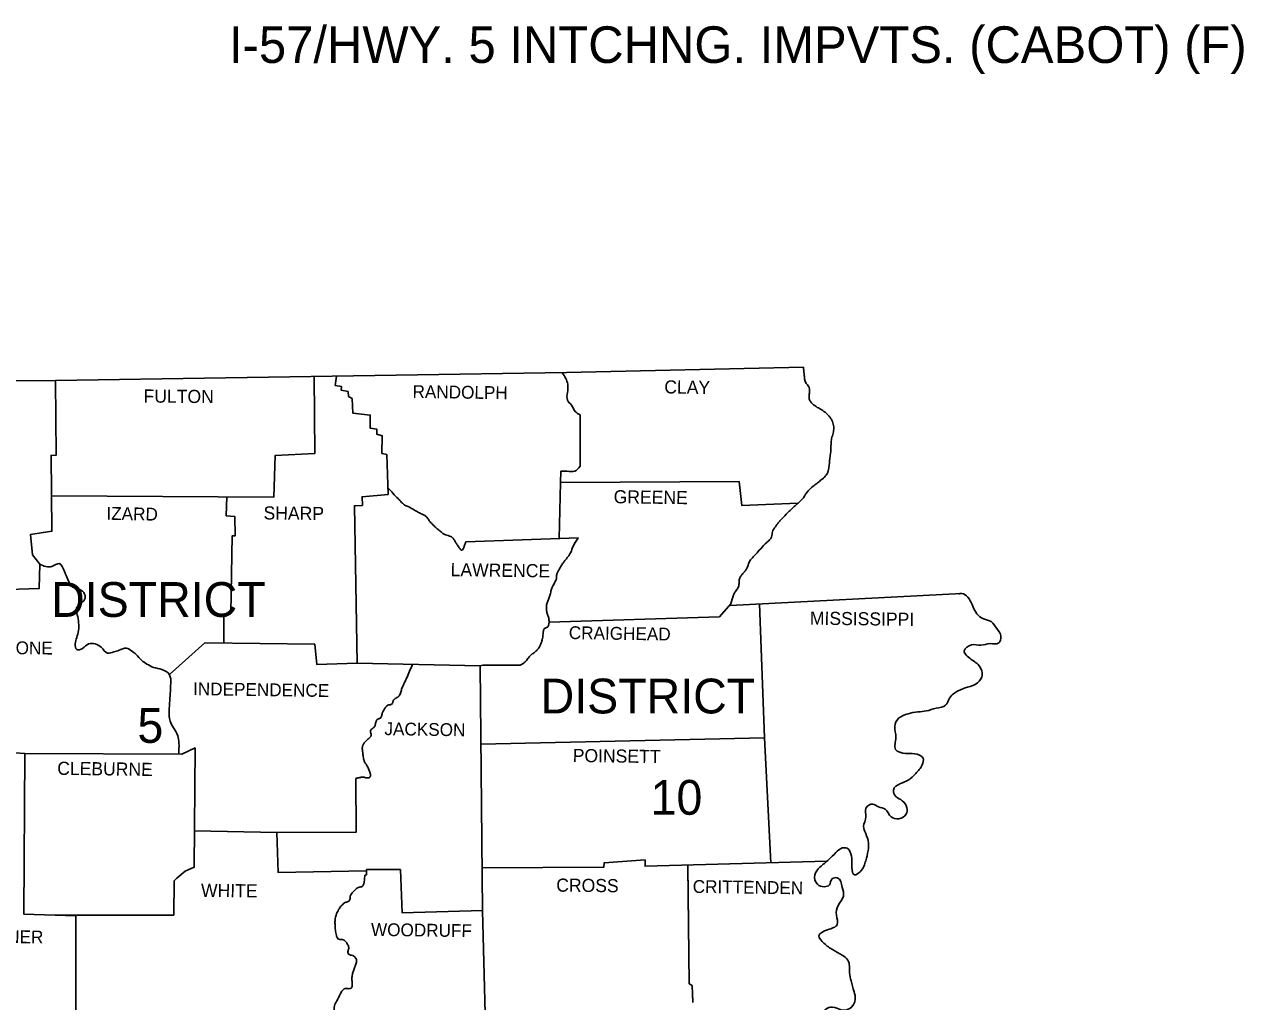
# Model space of a CAD drawing. Extents: x 1373878 to 1386598, y 1168333 to 1170533.
# Drawn here: x 1376588.9 to 1376988.4, y 1170078.1 to 1170398.3 of the extents above; entities that cross this region are included whole.
import ezdxf

# ---------------------------------------------------------------- set-up
doc = ezdxf.new("R2010")
doc.units = 0
for name, color, linetype in [('1', 7, 'Continuous'), ('Default', 7, 'Continuous'), ('G-ANNO-TEXT', 7, 'Continuous')]:
    doc.layers.add(name, color=color, linetype=linetype)

msp = doc.modelspace()

# ---------------------------------------------------------------- linework, layer by layer
at = {"layer": '1'}
for p, q in [((1376820.19, 1170207.9), (1376821.27, 1170211.22)), ((1376700.99, 1170121.31), (1376712.17, 1170121.31))]:
    msp.add_line(p, q, dxfattribs=at)
for points in [[(1376295.59, 1170281.4), (1376457.29, 1170281.3), (1376599.19, 1170281.6), (1376766.59, 1170284.2), (1376844.19, 1170286)], [(1376599.19, 1170281.6), (1376599.39, 1170257.2), (1376597.69, 1170257.1), (1376597.99, 1170232.2), (1376590.99, 1170231.2), (1376591.59, 1170224.5), (1376593.99, 1170221.4), (1376593.79, 1170213.5), (1376580.19, 1170213), (1376579.69, 1170200.8), (1376567.29, 1170200.4), (1376566.69, 1170185.61), (1376567.39, 1170184.41), (1376567.69, 1170160.81), (1376589.09, 1170159.41), (1376588.79, 1170106.71), (1376605.79, 1170106.21), (1376605.79, 1170052.61), (1376592.39, 1170051.61), (1376591.39, 1170039.81), (1376568.89, 1170039.71)], [(1376691.17, 1170283.03), (1376690.79, 1170280), (1376692.79, 1170279.7), (1376692.69, 1170278.5), (1376694.99, 1170278), (1376695.19, 1170276.4), (1376696.29, 1170275.7), (1376696.59, 1170270.9), (1376702.29, 1170270.3), (1376702.29, 1170266), (1376704.39, 1170265.7), (1376704.39, 1170264), (1376706.19, 1170263.5), (1376706.09, 1170257.7), (1376707.69, 1170257.4), (1376708.09, 1170244.3), (1376699.59, 1170243.5), (1376699.69, 1170240.7), (1376697.09, 1170240.6), (1376697.99, 1170189.01), (1376738.29, 1170188.11), (1376738.99, 1170107.91), (1376712.69, 1170107.21), (1376712.17, 1170121.31)], [(1376820.19, 1170207.9), (1376896.09, 1170211.8)], [(1376700.99, 1170121.31), (1376700.99, 1170119.61), (1376700.49, 1170119.51)], [(1376738.87, 1170121.9), (1376778.79, 1170122.11), (1376778.89, 1170123.51), (1376792.29, 1170124.51), (1376792.29, 1170122.41), (1376851.86, 1170124.04)]]:
    msp.add_lwpolyline(points, dxfattribs=at)
for points in [[(1376844.19, 1170286), (1376844.28, 1170284.9), (1376844.39, 1170283.8), (1376844.53, 1170282.7), (1376844.69, 1170281.6), (1376844.93, 1170280.98), (1376845.33, 1170280.42), (1376845.77, 1170279.88), (1376846.09, 1170279.3), (1376846.22, 1170278.29), (1376846.1, 1170277.19), (1376846.02, 1170276.1), (1376846.09, 1170275.59), (1376846.29, 1170275.1), (1376847.05, 1170274.12), (1376847.99, 1170273.3), (1376848.71, 1170272.83), (1376849.45, 1170272.41), (1376850.18, 1170271.99), (1376850.89, 1170271.5), (1376852.34, 1170270.22), (1376852.95, 1170269.48), (1376853.23, 1170269.06), (1376853.49, 1170268.6), (1376853.86, 1170267.76), (1376854.07, 1170266.9), (1376854.14, 1170266.05), (1376854.09, 1170265.2), (1376853.92, 1170264.33), (1376853.67, 1170263.46), (1376853.44, 1170262.59), (1376853.29, 1170261.7), (1376853.24, 1170260.73), (1376853.2, 1170259.76), (1376853.16, 1170258.78), (1376853.09, 1170257.8), (1376852.69, 1170254.4), (1376852.51, 1170252.84), (1376852.35, 1170252.07), (1376852.24, 1170251.68), (1376852.09, 1170251.3), (1376851.05, 1170249.92), (1376849.69, 1170248.8), (1376849.12, 1170248.35), (1376848.54, 1170247.91), (1376847.96, 1170247.47), (1376847.39, 1170247), (1376845.29, 1170244.9), (1376844.9, 1170244.36), (1376844.56, 1170243.78), (1376844.21, 1170243.21), (1376843.79, 1170242.7), (1376841.19, 1170240.3), (1376838.59, 1170237.8), (1376836.49, 1170235.6), (1376835.92, 1170234.94), (1376835.38, 1170234.25), (1376834.88, 1170233.53), (1376834.39, 1170232.8), (1376834.09, 1170232.05), (1376833.94, 1170231.22), (1376833.77, 1170230.41), (1376833.62, 1170230.04), (1376833.39, 1170229.7), (1376832.84, 1170229.13), (1376832.25, 1170228.6), (1376831.65, 1170228.07), (1376831.09, 1170227.5), (1376829.29, 1170225.5), (1376826.89, 1170222.8), (1376826.5, 1170222.19), (1376826.23, 1170221.49), (1376825.99, 1170220.78), (1376825.69, 1170220.1), (1376825.16, 1170219.31), (1376824.53, 1170218.57), (1376823.91, 1170217.81), (1376823.39, 1170217), (1376823.18, 1170216.29), (1376823.12, 1170215.51), (1376823.07, 1170214.73), (1376822.89, 1170214), (1376822.57, 1170213.38), (1376822.17, 1170212.79), (1376821.76, 1170212.2), (1376821.39, 1170211.6), (1376821.27, 1170211.22)], [(1376894.99, 1170211.7), (1376896.09, 1170211.8), (1376899.49, 1170208.2), (1376900.99, 1170205.2), (1376903.19, 1170203.5), (1376905.69, 1170202.6), (1376907.59, 1170200.3), (1376908.89, 1170197.8), (1376908.19, 1170195.6), (1376905.39, 1170195.4), (1376902.29, 1170194.9), (1376899.29, 1170195), (1376896.89, 1170193), (1376899.09, 1170190.31), (1376901.99, 1170187.81), (1376902.79, 1170185.11), (1376901.19, 1170182.51), (1376897.99, 1170181.11), (1376894.89, 1170179.91), (1376892.09, 1170177.51), (1376890.79, 1170175.21), (1376887.69, 1170174.21), (1376884.49, 1170173.31), (1376881.69, 1170173.01), (1376878.49, 1170172.41), (1376875.39, 1170170.91), (1376874.09, 1170168.31), (1376874.49, 1170164.61), (1376874.39, 1170160.71), (1376877.69, 1170159.41), (1376880.59, 1170159.31), (1376883.39, 1170157.81), (1376883.09, 1170155.61), (1376880.99, 1170152.81), (1376878.49, 1170150.61), (1376875.99, 1170149.51), (1376873.69, 1170147.41), (1376874.49, 1170145.31), (1376876.59, 1170143.91), (1376878.09, 1170141.61), (1376877.89, 1170139.51), (1376875.49, 1170138.01), (1376872.89, 1170138.61), (1376870.99, 1170141.11), (1376868.79, 1170141.91), (1376866.89, 1170142.81), (1376864.69, 1170141.51), (1376864.69, 1170138.61), (1376863.89, 1170135.51), (1376864.59, 1170133.21), (1376865.49, 1170130.01), (1376865.39, 1170127.61), (1376864.59, 1170124.21), (1376862.89, 1170120.71), (1376860.89, 1170119.61), (1376860.09, 1170123.41), (1376859.69, 1170126.51), (1376858.49, 1170128.31), (1376856.89, 1170128.41), (1376854.79, 1170126.91), (1376852.49, 1170124.61), (1376849.59, 1170122.11), (1376847.89, 1170119.61), (1376848.79, 1170116.51), (1376850.99, 1170115.71), (1376852.69, 1170116.31), (1376853.59, 1170118.31), (1376855.29, 1170118.61), (1376856.89, 1170115.51)], [(1376700.49, 1170119.51), (1376700.43, 1170118.68), (1376700.36, 1170117.85), (1376700.22, 1170117.02), (1376700.12, 1170116.61), (1376700.06, 1170116.41), (1376699.99, 1170116.21), (1376699.67, 1170115.84), (1376699.16, 1170115.66), (1376698.59, 1170115.53), (1376698.32, 1170115.44), (1376698.09, 1170115.31), (1376696.92, 1170114.28), (1376695.89, 1170113.11), (1376695.7, 1170112.64), (1376695.66, 1170112.09), (1376695.6, 1170111.56), (1376695.39, 1170111.11), (1376695.21, 1170110.95), (1376695, 1170110.84), (1376694.51, 1170110.7), (1376694.01, 1170110.56), (1376693.59, 1170110.31), (1376693.12, 1170109.83), (1376692.67, 1170109.33), (1376692.26, 1170108.79), (1376691.89, 1170108.21), (1376691.21, 1170106.79), (1376690.79, 1170105.31), (1376690.71, 1170103.81), (1376690.79, 1170102.31), (1376690.86, 1170101.44), (1376690.98, 1170100.59), (1376691.18, 1170099.74), (1376691.32, 1170099.32), (1376691.49, 1170098.91), (1376691.96, 1170098.51), (1376692.65, 1170098.39), (1376693.39, 1170098.31), (1376693.99, 1170098.01), (1376694.19, 1170097.78), (1376694.38, 1170097.55), (1376694.7, 1170097.05), (1376695.19, 1170096.01), (1376695.22, 1170095.49), (1376695.07, 1170094.94), (1376694.94, 1170094.4), (1376694.99, 1170093.91), (1376695.46, 1170093.47), (1376696.15, 1170093.23), (1376696.86, 1170092.98), (1376697.39, 1170092.51), (1376697.57, 1170092.21), (1376697.72, 1170091.91), (1376697.81, 1170091.61), (1376697.79, 1170091.31), (1376697.39, 1170090.01), (1376696.29, 1170086.31), (1376696.22, 1170085.69), (1376696.27, 1170085.07), (1376696.35, 1170084.44), (1376696.39, 1170083.81), (1376696.35, 1170083.25), (1376696.29, 1170082.98), (1376696.19, 1170082.71), (1376695.67, 1170082.33), (1376694.87, 1170082.32), (1376694.06, 1170082.33), (1376693.49, 1170082.01), (1376691.89, 1170079.31), (1376690.79, 1170077.41), (1376690.66, 1170077.1), (1376690.45, 1170076.16), (1376690.41, 1170075.54), (1376690.39, 1170074.91), (1376690.44, 1170074.46), (1376690.57, 1170074.01), (1376690.68, 1170073.56), (1376690.69, 1170073.11), (1376690.55, 1170072.74), (1376690.32, 1170072.4), (1376690.07, 1170072.06), (1376689.89, 1170071.71), (1376689.81, 1170071.19), (1376689.8, 1170070.65), (1376689.75, 1170070.11), (1376689.59, 1170069.61), (1376688.59, 1170067.81), (1376687.69, 1170066.11), (1376687.73, 1170065.62), (1376688.12, 1170065.12), (1376688.55, 1170064.62), (1376688.69, 1170064.11), (1376688.55, 1170063.42), (1376688.39, 1170062.71), (1376688.24, 1170062.15), (1376688.06, 1170061.6), (1376687.79, 1170060.51)], [(1376856.89, 1170115.51), (1376857.29, 1170112.61), (1376855.59, 1170109.51), (1376854.99, 1170106.41), (1376855.29, 1170103.31), (1376852.09, 1170101.61), (1376849.29, 1170099.61), (1376850.89, 1170097.21), (1376853.89, 1170095.01), (1376856.89, 1170093.31), (1376858.79, 1170091.61), (1376859.29, 1170087.51), (1376859.79, 1170084.91), (1376860.79, 1170081.31), (1376861.19, 1170078.81), (1376859.39, 1170075.81), (1376857.29, 1170075.21), (1376855.09, 1170075.91), (1376852.49, 1170076.11), (1376850.39, 1170074.11), (1376848.89, 1170071.31), (1376847.39, 1170068.51), (1376846.29, 1170066.11), (1376845.19, 1170063.51), (1376842.99, 1170060.51), (1376840.29, 1170060.01), (1376837.09, 1170059.21), (1376835.19, 1170057.01), (1376835.49, 1170053.31), (1376837.29, 1170050.81), (1376838.69, 1170047.71), (1376839.69, 1170045.01), (1376839.19, 1170041.61), (1376837.79, 1170039.11), (1376835.99, 1170037.61), (1376835.19, 1170034.41), (1376833.89, 1170032.01), (1376832.69, 1170031.21), (1376830.29, 1170031.41), (1376827.69, 1170031.91), (1376825.49, 1170031.71), (1376823.39, 1170030.61), (1376821.29, 1170031.31), (1376819.09, 1170033.71), (1376817.29, 1170035.51), (1376815.29, 1170036.21), (1376813.19, 1170035.11), (1376812.79, 1170031.81), (1376813.79, 1170028.41), (1376814.69, 1170023.81), (1376813.79, 1170021.01), (1376813.49, 1170016.41)]]:
    msp.add_spline(points, degree=3, dxfattribs=at)
at = {"layer": 'Default'}
msp.add_line((1376764.6, 1170248.2), (1376764.69, 1170251.9), dxfattribs=at)
for points in [[(1376683.89, 1170282.92), (1376684.09, 1170257.7), (1376671.09, 1170257), (1376670.69, 1170243.4), (1376597.85, 1170243.81)], [(1376770.99, 1170270.4), (1376770.99, 1170253.5)], [(1376764.17, 1170229.88), (1376764.6, 1170248.2), (1376764.69, 1170248.2), (1376823.19, 1170248.5), (1376823.99, 1170240.7), (1376842.34, 1170241.37)], [(1376655.31, 1170243.49), (1376655.09, 1170237.3), (1376657.89, 1170237.1), (1376657.99, 1170230.7), (1376656.99, 1170230.7), (1376656.59, 1170205.5), (1376654.29, 1170204.5), (1376654.29, 1170195.62)], [(1376733.59, 1170228.8), (1376770.46, 1170230.1)], [(1376760.85, 1170202.39), (1376816.69, 1170204.2), (1376820.36, 1170208.43)], [(1376829.77, 1170208.4), (1376831.49, 1170164.51), (1376833.53, 1170123.54)], [(1376636.49, 1170185.22), (1376648.09, 1170195.7), (1376684.09, 1170195.2), (1376684.79, 1170188.51), (1376697.99, 1170189.01)], [(1376751.39, 1170188.31), (1376739.19, 1170188.31), (1376738.29, 1170188.11)], [(1376831.49, 1170164.51), (1376738.52, 1170162.39)], [(1376589.09, 1170159.41), (1376640.49, 1170159.11), (1376644.89, 1170161.21), (1376644.59, 1170122.11), (1376641.59, 1170120.81), (1376638.89, 1170118.51), (1376637.99, 1170117.61), (1376637.89, 1170106.41), (1376598.99, 1170106.41)], [(1376697.49, 1170151.21), (1376697.69, 1170133.61), (1376671.69, 1170133.51), (1376644.68, 1170134.01)], [(1376671.69, 1170133.51), (1376672.09, 1170120.41), (1376700.99, 1170120.92)], [(1376806.29, 1170122.79), (1376806.79, 1170083.91), (1376807.69, 1170083.31), (1376808.01, 1170077.77)], [(1376806.29, 1170122.41), (1376806.79, 1170083.91), (1376807.69, 1170083.31), (1376807.99, 1170078.11)], [(1376806.29, 1170122.41), (1376806.79, 1170083.91), (1376807.69, 1170083.31), (1376807.99, 1170078.11)], [(1376806.29, 1170122.41), (1376806.79, 1170083.91), (1376807.69, 1170083.31), (1376807.99, 1170078.11)], [(1376806.29, 1170122.41), (1376806.79, 1170083.91), (1376807.69, 1170083.31), (1376807.99, 1170078.11)], [(1376738.99, 1170107.91), (1376740.49, 1170053.11), (1376716.69, 1170053.01), (1376716.59, 1170050.81), (1376709.69, 1170050.41), (1376709.09, 1170039.01), (1376699.61, 1170039.01)]]:
    msp.add_lwpolyline(points, dxfattribs=at)
for points in [[(1376765.18, 1170284.18), (1376766.99, 1170280.4), (1376766.89, 1170277.7), (1376766.89, 1170275.2), (1376768.19, 1170273.5), (1376769.49, 1170271.4), (1376770.99, 1170270.4)], [(1376770.99, 1170253.5), (1376769.29, 1170251.9), (1376766.79, 1170251.9), (1376764.69, 1170251.9)], [(1376708.03, 1170246.41), (1376709.7, 1170244.65), (1376711.39, 1170242.9), (1376711.63, 1170242.66), (1376712.32, 1170241.93), (1376712.79, 1170241.46), (1376713.04, 1170241.23), (1376713.16, 1170241.11), (1376713.29, 1170241), (1376713.8, 1170240.66), (1376714.36, 1170240.41), (1376714.94, 1170240.17), (1376715.49, 1170239.9), (1376716.79, 1170239.15), (1376718.09, 1170238.4), (1376718.67, 1170238.1), (1376719.25, 1170237.83), (1376720.12, 1170237.38), (1376720.26, 1170237.29), (1376720.39, 1170237.2), (1376720.83, 1170236.8), (1376721.19, 1170236.3), (1376721.52, 1170235.78), (1376721.7, 1170235.53), (1376721.89, 1170235.3), (1376722.93, 1170234.24), (1376723.99, 1170233.2), (1376724.5, 1170232.75), (1376725.02, 1170232.32), (1376725.56, 1170231.91), (1376726.09, 1170231.5), (1376726.91, 1170231.08), (1376727.82, 1170230.79), (1376728.69, 1170230.46), (1376729.07, 1170230.22), (1376729.24, 1170230.07), (1376729.39, 1170229.9), (1376729.69, 1170229.49), (1376729.96, 1170229.06), (1376730.22, 1170228.63), (1376730.49, 1170228.2), (1376730.68, 1170227.93), (1376730.87, 1170227.64), (1376731.24, 1170227.05), (1376731.62, 1170226.52), (1376731.81, 1170226.29), (1376731.9, 1170226.19), (1376731.95, 1170226.15), (1376731.99, 1170226.1), (1376732.11, 1170226.03), (1376732.22, 1170226.02), (1376732.44, 1170226.15), (1376732.88, 1170226.87), (1376733.27, 1170227.87), (1376733.44, 1170228.37), (1376733.59, 1170228.8)], [(1376770.46, 1170230.1), (1376769.62, 1170228.88), (1376768.89, 1170227.6), (1376768.58, 1170226.91), (1376768.31, 1170226.19), (1376768.04, 1170225.48), (1376767.69, 1170224.8), (1376767.13, 1170223.98), (1376766.52, 1170223.19), (1376765.89, 1170222.41), (1376765.29, 1170221.6), (1376764.33, 1170220.09), (1376763.89, 1170219.31), (1376763.49, 1170218.5), (1376763.36, 1170218), (1376763.33, 1170217.46), (1376763.3, 1170216.92), (1376763.19, 1170216.4), (1376762.87, 1170215.7), (1376762.48, 1170215.01), (1376762.1, 1170214.32), (1376761.79, 1170213.6), (1376761.58, 1170212.91), (1376761.39, 1170212.2), (1376761.2, 1170211.5), (1376760.99, 1170210.8), (1376760.78, 1170210.2), (1376760.53, 1170209.61), (1376760.3, 1170209.01), (1376760.09, 1170208.4), (1376759.98, 1170207.79), (1376759.97, 1170207.16), (1376760.01, 1170206.53), (1376760.09, 1170205.9), (1376760.23, 1170205.28), (1376760.43, 1170204.65), (1376760.64, 1170204.03), (1376760.79, 1170203.4), (1376760.85, 1170202.84), (1376760.84, 1170202.25), (1376760.75, 1170201.67), (1376760.68, 1170201.39), (1376760.59, 1170201.1), (1376760.29, 1170200.76), (1376759.82, 1170200.55), (1376759.36, 1170200.34), (1376759.09, 1170200), (1376759.02, 1170199.65), (1376758.96, 1170199.29), (1376758.89, 1170198.56), (1376758.82, 1170197.82), (1376758.69, 1170197.1), (1376758.43, 1170196.1), (1376758.09, 1170195.1), (1376757.54, 1170194.04), (1376757.19, 1170193.56), (1376756.79, 1170193.1), (1376756.34, 1170192.7), (1376755.85, 1170192.34), (1376755.35, 1170191.99), (1376754.89, 1170191.61), (1376754.38, 1170191.05), (1376753.9, 1170190.46), (1376753.42, 1170189.87), (1376752.89, 1170189.31), (1376752.19, 1170188.75), (1376751.81, 1170188.52), (1376751.39, 1170188.31)], [(1376593.99, 1170221.4), (1376597.99, 1170220.7), (1376600.39, 1170221.6), (1376602.09, 1170219), (1376602.99, 1170217), (1376604.49, 1170214.1), (1376606.89, 1170213.2), (1376608.69, 1170211.6), (1376608.69, 1170209.9), (1376607.09, 1170208.3), (1376605.89, 1170206.7), (1376606.29, 1170204.8), (1376606.69, 1170202.2), (1376606.69, 1170199.7), (1376606.09, 1170197.4), (1376605.59, 1170195.3), (1376606.09, 1170193.5), (1376607.99, 1170193.8), (1376609.99, 1170195.3), (1376612.09, 1170195.3), (1376614.09, 1170194.2), (1376616.19, 1170192.3), (1376618.29, 1170192.7), (1376619.99, 1170193.21), (1376622.39, 1170193.9), (1376624.09, 1170193), (1376625.59, 1170191.81), (1376627.39, 1170189.91), (1376629.09, 1170188.71), (1376631.29, 1170187.61), (1376633.99, 1170186.91), (1376636.49, 1170185.21), (1376636.89, 1170182.31), (1376636.79, 1170179.81), (1376636.59, 1170176.71), (1376636.39, 1170173.31), (1376636.69, 1170170.01), (1376637.79, 1170167.81), (1376639.19, 1170165.21), (1376639.59, 1170162.81), (1376639.49, 1170159.01)], [(1376716.06, 1170188.6), (1376715.16, 1170186.34), (1376714.19, 1170184.11), (1376713.85, 1170183.35), (1376713.49, 1170182.6), (1376713.14, 1170181.86), (1376712.79, 1170181.11), (1376712.55, 1170180.46), (1376712.35, 1170179.8), (1376712.14, 1170179.15), (1376711.89, 1170178.51), (1376711.52, 1170178.04), (1376711, 1170177.7), (1376710.45, 1170177.38), (1376710.2, 1170177.21), (1376709.99, 1170177.01), (1376709.82, 1170176.68), (1376709.7, 1170176.3), (1376709.59, 1170175.92), (1376709.39, 1170175.61), (1376709.01, 1170175.4), (1376708.54, 1170175.32), (1376708.07, 1170175.23), (1376707.69, 1170175.01), (1376707.5, 1170174.78), (1376707.32, 1170174.54), (1376706.98, 1170174.05), (1376706.67, 1170173.53), (1376706.39, 1170173.01), (1376706.22, 1170172.56), (1376706.1, 1170172.1), (1376705.97, 1170171.64), (1376705.79, 1170171.21), (1376705.51, 1170170.94), (1376705.11, 1170170.79), (1376704.7, 1170170.64), (1376704.39, 1170170.41), (1376704.26, 1170170.16), (1376704.16, 1170169.89), (1376704.02, 1170169.31), (1376703.9, 1170168.72), (1376703.76, 1170168.32), (1376703.69, 1170168.21), (1376703.41, 1170167.89), (1376703.04, 1170167.61), (1376702.67, 1170167.33), (1376702.39, 1170167.01), (1376702.34, 1170166.53), (1376702.48, 1170165.99), (1376702.61, 1170165.46), (1376702.49, 1170165.01), (1376702.41, 1170164.91), (1376702.33, 1170164.82), (1376701.75, 1170164.3), (1376701.36, 1170163.97), (1376700.99, 1170163.61), (1376700.65, 1170163.24), (1376700.31, 1170162.86), (1376700.01, 1170162.46), (1376699.89, 1170162.24), (1376699.79, 1170162.01), (1376699.67, 1170160.91), (1376699.79, 1170159.81), (1376699.87, 1170159.08), (1376699.95, 1170158.35), (1376700.08, 1170157.62), (1376700.17, 1170157.26), (1376700.29, 1170156.91), (1376700.51, 1170156.46), (1376700.77, 1170156.04), (1376701.05, 1170155.63), (1376701.29, 1170155.21), (1376701.78, 1170154.11), (1376701.99, 1170153.56), (1376702.19, 1170153.01), (1376702.31, 1170152.65), (1376702.37, 1170152.27), (1376702.32, 1170151.91), (1376702.23, 1170151.75), (1376702.17, 1170151.67), (1376702.09, 1170151.61), (1376701.48, 1170151.37), (1376700.85, 1170151.43), (1376700.22, 1170151.58), (1376699.9, 1170151.62), (1376699.59, 1170151.61), (1376699.07, 1170151.52), (1376698.54, 1170151.43), (1376698.02, 1170151.33), (1376697.49, 1170151.21)]]:
    msp.add_spline(points, degree=3, dxfattribs=at)

# ---------------------------------------------------------------- texts
for s, height, rotation, p in [('CLAY', 4.299, 359.2258, (1376798.59, 1170277.4)), ('FULTON', 4.299, 359.4996, (1376627.99, 1170274.4)), ('RANDOLPH', 4.2, 359.2584, (1376716.09, 1170275.9)), ('GREENE', 4.301, 359.2361, (1376781.99, 1170241.4)), ('SHARP', 4.299, 359.3905, (1376667.29, 1170236.1)), ('IZARD', 4.199, 358.9259, (1376615.79, 1170236)), ('LAWRENCE', 4.301, 359.2678, (1376728.59, 1170217.5)), ('MISSISSIPPI', 4.2994, 359.3097, (1376846.29, 1170201.6)), ('CRAIGHEAD', 4.2, 359.1159, (1376767.29, 1170196.9)), ('STONE', 4.199, 359.4001, (1376578.89, 1170192.01)), ('INDEPENDENCE', 4.1992, 359.2188, (1376644.19, 1170178.51)), ('JACKSON', 4.199, 359.1352, (1376706.89, 1170165.41)), ('POINSETT', 4.299, 359.1987, (1376768.59, 1170156.61)), ('CLEBURNE', 4.299, 359.2535, (1376599.69, 1170152.41)), ('WHITE', 4.301, 359.3139, (1376646.79, 1170112.41)), ('CROSS', 4.299, 359.384, (1376763.19, 1170114.11)), ('CRITTENDEN', 4.2, 359.213, (1376807.89, 1170113.71)), ('FAULKNER', 4.2, 359.2486, (1376565.19, 1170097.51)), ('WOODRUFF', 4.199, 359.2748, (1376702.49, 1170099.61))]:
    msp.add_text(s, height=height, rotation=rotation, dxfattribs=at).set_placement(p)
for s, p in [('DISTRICT', (1376597.71, 1170204.15)), ('DISTRICT', (1376758.09, 1170172.51)), ('5', (1376625.98, 1170162.87)), ('10', (1376794.12, 1170139.31))]:
    msp.add_text(s, height=11.4, dxfattribs=at).set_placement(p)
at = {"layer": 'G-ANNO-TEXT'}
msp.add_text('I-57/HWY. 5 INTCHNG. IMPVTS. (CABOT) (F)', height=12, dxfattribs=at).set_placement((1376655.99, 1170385.7))

doc.saveas('drawing.dxf')
